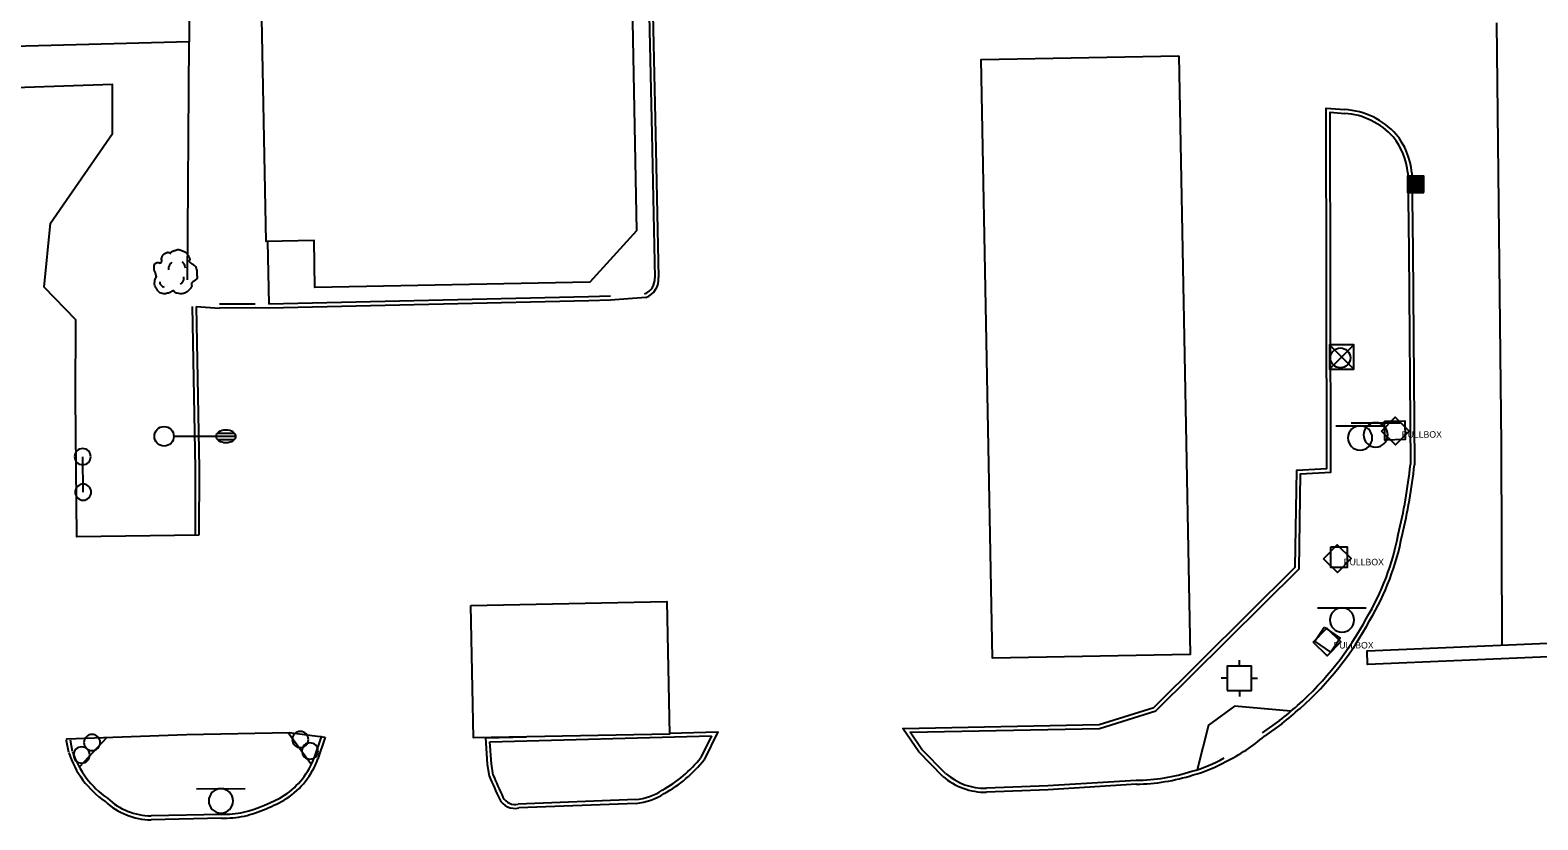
# Model space of a CAD drawing. Extents: x 2145380 to 2157287, y 139568 to 149130.
# Drawn here: x 2150453.6 to 2150685.4, y 145669.1 to 145790.5 of the extents above; entities that cross this region are included whole.
import ezdxf

# ---------------------------------------------------------------- set-up
doc = ezdxf.new("R2010")
doc.units = 0
for name, color, linetype in [('Default', 7, 'Continuous'), ('TOPO_Asphalt', 7, 'Continuous'), ('TOPO_Building', 7, 'Continuous'), ('TOPO_Concrete', 7, 'Continuous'), ('TOPO_Curb Back', 7, 'Continuous'), ('TOPO_Fence', 7, 'Continuous'), ('TOPO_Light Pole', 7, 'Continuous'), ('TOPO_Misc', 7, 'Continuous'), ('TOPO_Misc Line', 7, 'Continuous'), ('TOPO_Power Pullbox', 7, 'Continuous'), ('TOPO_Sidewalk', 7, 'Continuous'), ('TOPO_Sign', 7, 'Continuous'), ('TOPO_Traffic Signal', 7, 'Continuous'), ('TOPO_Tree', 7, 'Continuous'), ('TOPO_Wall Freestanding', 7, 'Continuous'), ('TOPO_Water Meter', 7, 'Continuous')]:
    doc.layers.add(name, color=color, linetype=linetype)

# ---------------------------------------------------------------- blocks, each defined once
blk = doc.blocks.new('TRFSIG')
at = {"layer": 'TOPO_Traffic Signal'}
for p, q in [((0.04, 4.66), (0.04, 7.04)), ((-4.7, -0.09), (-7.08, -0.09)), ((0.04, -4.83), (0.04, -7.22)), ((4.79, -0.09), (7.17, -0.09))]:
    blk.add_line(p, q, dxfattribs=at)
blk.add_lwpolyline([(-4.7, -4.85), (4.81, -4.83), (4.79, 4.67), (-4.72, 4.66), (-4.7, -4.85)], dxfattribs=at)
blk = doc.blocks.new('LP')
at = {"layer": 'TOPO_Light Pole'}
blk.add_line((3.81, 0), (20.32, 0), dxfattribs=at)
for points in [[(20.32, 0), (27.94, 0)], [(20.32, 0), (23.5, 0)], [(20.83, 1.27), (27.43, 1.27)], [(20.83, 1.27), (23.5, 1.27)], [(23.71, 1.27), (27.43, 1.27)], [(23.71, 0), (27.94, 0)], [(20.83, -1.27), (27.43, -1.27)], [(20.83, -1.27), (23.5, -1.27)], [(23.71, -1.27), (27.43, -1.27)]]:
    blk.add_lwpolyline(points, dxfattribs=at)
blk.add_circle((0, 0), 3.81, dxfattribs=at)
blk.add_ellipse((24.13, 0), major_axis=(3.81, 0), ratio=0.666667, dxfattribs=at)
blk = doc.blocks.new('POST')
at = {"layer": 'TOPO_Misc'}
for start, end in [(89.99996, 180.00004), (179.99996, 270.00004), (359.99996, 90.00004), (269.99996, 0.00004)]:
    blk.add_arc((-0.01, 0.03), 3.16, start, end, dxfattribs=at)
blk = doc.blocks.new('CB')
at = {"layer": 'TOPO_Misc'}
for p, q in [((-3.08, 2.99), (3.24, 2.99)), ((-3.08, 2.68), (3.24, 2.68)), ((-3.08, 2.36), (3.24, 2.36)), ((-3.08, 2.05), (3.24, 2.05)), ((-3.08, 1.73), (3.24, 1.73)), ((-3.08, 1.4), (3.24, 1.4)), ((-3.08, 1.1), (3.24, 1.1)), ((-3.08, 0.77), (3.24, 0.77)), ((-3.08, 0.46), (3.24, 0.46)), ((-3.08, 0.14), (3.24, 0.14)), ((-3.08, -0.17), (3.24, -0.17)), ((-3.08, -0.48), (3.24, -0.48)), ((-3.08, -0.8), (3.24, -0.8)), ((-3.08, -1.11), (3.26, -1.11)), ((-3.08, -1.43), (3.26, -1.43)), ((-3.08, -1.75), (3.26, -1.75)), ((-3.08, -2.07), (3.26, -2.07)), ((-3.08, -2.39), (3.26, -2.39)), ((-3.08, -2.7), (3.26, -2.7)), ((-3.08, -3.02), (3.26, -3.02))]:
    blk.add_line(p, q, dxfattribs=at)
blk.add_lwpolyline([(3.26, -3.29), (3.24, 3.05), (-3.09, 3.04), (-3.08, -3.3), (3.26, -3.29)], dxfattribs=at)
blk = doc.blocks.new('TREE')
at = {"layer": 'TOPO_Tree'}
for points in [[(-14.1, -0.4), (-14.2, 0.5), (-14.4, 1.4), (-14.6, 2.3), (-14.8, 3.2), (-15.5, 4), (-15.7, 4.9), (-15.8, 5.6), (-15.7, 6.3), (-15.7, 7), (-15.6, 7.9), (-15.7, 8.8), (-15.1, 9.7), (-14.6, 10.4), (-13.8, 10.5), (-13, 10.7), (-12.2, 11), (-11.1, 10), (-10.4, 10.7), (-9.4, 11.7), (-10.3, 13.3), (-9.8, 14.4), (-9.6, 15.1), (-9.3, 15.9), (-8.8, 16.5), (-8.2, 17.3), (-7.5, 17.7), (-6.7, 18.1), (-6.1, 18.4), (-5.6, 18.6), (-5.1, 18.7), (-4.5, 18.7), (-4, 18.5), (-3.5, 18.1)], [(-3.5, 17.6), (-3.1, 18.3), (-2.6, 18.8), (-1.9, 19.2), (-1, 19.7), (-0.2, 20), (0.7, 20.2), (1.6, 20.5), (2.5, 20.8), (3.4, 20.8), (4.1, 20.7), (4.8, 20.5), (5.5, 20.2), (6.4, 19.9), (7.3, 19.7), (8.2, 19.2), (9.4, 18.4), (10, 17.2), (10.8, 16), (11.2, 15.3), (11.6, 14.6), (11.9, 13.9), (12.2, 13.1), (11.4, 12), (11.9, 11.2), (12, 11), (12.2, 10.9), (12.4, 10.7), (12.9, 10.4), (13.5, 10), (14, 9.7), (14.7, 9.2), (15.4, 8.7), (16.1, 8.1), (16.7, 7.5), (16.9, 6.7), (17.1, 6), (17.6, 4.4), (17.7, 2.8), (17.7, 1.2), (17.7, -0.2), (17.8, -2.2), (16.6, -3), (15.5, -3.8), (14.3, -4.6), (13.2, -5.3)], [(13.2, -5.3), (13.3, -5.8), (13.4, -6.3), (13.4, -6.7), (13.8, -8.5), (12.2, -10), (10.8, -11.5), (10, -12.3), (9.1, -12.8), (8.2, -13.1), (6, -13.8), (3.3, -13.6), (1.3, -13.1), (0.5, -12.9), (-0.1, -11.4), (-0.8, -11.5), (-2, -11.6), (-3.3, -12.8), (-4.5, -13.1), (-6.1, -13.5), (-7.8, -14), (-9.3, -13.6), (-11.4, -13.1), (-12.8, -11.4), (-14.1, -9.4), (-15.3, -7.3), (-15.6, -5.1), (-15.1, -3), (-14.9, -1.9), (-13.9, -0.8), (-13.5, 0.1)], [(-4.2, 5.1), (-4.5, 6.1), (-4.3, 7.2), (-3.8, 8.2), (-3.3, 9.3), (-2.7, 10.3), (-1.6, 11)], [(5.9, 11.2), (6.5, 10.7), (7, 10.2), (7.4, 9.5), (7.9, 8.6), (8.3, 7.6), (8.5, 6.6)], [(-11.4, -4.5), (-11.5, -5.4), (-11, -6.3), (-10.1, -7.2), (-9.3, -8), (-8.5, -8.3), (-7.7, -8.1)], [(4.8, -6.3), (5.7, -5.7), (6.3, -4.9), (6.8, -3.9), (7.4, -2.8), (7.6, -1.7), (7.5, -0.6)]]:
    blk.add_open_spline(points, degree=3, dxfattribs=at)
blk = doc.blocks.new('pulbox')
at = {"layer": 'Default'}
blk.add_lwpolyline([(-5.38, -0.01), (-0.02, 5.42), (5.4, 0.06), (0.05, -5.36), (-5.38, -0.01)], dxfattribs=at)
blk.add_text('PULLBOX', height=2.54, dxfattribs=at).set_placement((2.54, -2.54))
blk = doc.blocks.new('WTRMTR')
at = {"layer": 'Default'}
blk.add_circle((0, 0), 3.89, dxfattribs=at)

msp = doc.modelspace()

# ---------------------------------------------------------------- linework, layer by layer
at = {"layer": 'TOPO_Asphalt'}
for p, q in [((2150479.12, 145747.97), (2150482.74, 145747.74)), ((2150490.31, 145747.73), (2150488.21, 145747.76)), ((2150548.29, 145749.38), (2150542.86, 145748.97))]:
    msp.add_line(p, q, dxfattribs=at)
for points in [[(2150479.57, 145712.84), (2150460.77, 145712.55), (2150460.61, 145734), (2150460.65, 145745.93), (2150455.78, 145750.97), (2150456.76, 145760.81), (2150466.27, 145774.6), (2150466.27, 145782.09), (2150445.27, 145781.39)], [(2150459.22, 145681.2), (2150459.23, 145681.51), (2150477.67, 145682.19), (2150493.45, 145682.52), (2150498.99, 145681.78)]]:
    msp.add_lwpolyline(points, dxfattribs=at)
msp.add_arc((2150626.83, 145700.66), 24.98, 295.202, 311.4607, dxfattribs=at)
at = {"layer": 'TOPO_Building'}
msp.add_lwpolyline([(2150545.73, 145818.58), (2150546.85, 145759.6), (2150539.66, 145751.71), (2150497.4, 145750.91), (2150497.26, 145758.14), (2150489.89, 145758), (2150488.64, 145824), (2150538.35, 145824.95), (2150538.47, 145818.44)], close=True, dxfattribs=at)
at = {"layer": 'TOPO_Concrete'}
for p, q in [((2150465.41, 145681.74), (2150461.17, 145677.17)), ((2150493.26, 145682.52), (2150496.85, 145677.59))]:
    msp.add_line(p, q, dxfattribs=at)
for points in [[(2150661.83, 145730.35), (2150664.95, 145730.43), (2150665.03, 145727.53), (2150661.91, 145727.44), (2150661.83, 145730.35)], [(2150653.57, 145711.03), (2150656.09, 145711.03), (2150656.1, 145707.88), (2150653.58, 145707.87), (2150653.57, 145711.03)], [(2150652.59, 145698.68), (2150655.04, 145697.01), (2150653.58, 145694.86), (2150651.13, 145696.52), (2150652.59, 145698.68)]]:
    msp.add_lwpolyline(points, dxfattribs=at)
at = {"layer": 'TOPO_Curb Back'}
for p, q in [((2150488.2, 145748.36), (2150482.74, 145748.34)), ((2150488.21, 145747.76), (2150482.74, 145747.74)), ((2150524.31, 145681.07), (2150558.35, 145681.99)), ((2150524.53, 145677.69), (2150524.31, 145681.07)), ((2150558.35, 145681.99), (2150556.73, 145678.63)), ((2150524.81, 145675.91), (2150524.53, 145677.69)), ((2150546.73, 145672.19), (2150528.67, 145671.49))]:
    msp.add_line(p, q, dxfattribs=at)
for points in [[(2150538.35, 145824.79), (2150548.63, 145825.11), (2150549.78, 145774.55), (2150550.24, 145752.43)], [(2150538.37, 145824.19), (2150548.05, 145824.49), (2150549.18, 145774.54), (2150549.64, 145752.4)], [(2150593.96, 145675.75), (2150590.24, 145679.51), (2150587.77, 145683.13), (2150617.99, 145683.73), (2150626.37, 145686.33), (2150648.12, 145707.9), (2150648.34, 145722.81), (2150653, 145723.08), (2150652.87, 145778.49), (2150655.76, 145778.27)], [(2150594.37, 145676.19), (2150590.7, 145679.9), (2150588.89, 145682.55), (2150618.05, 145683.13), (2150626.69, 145685.8), (2150648.71, 145707.65), (2150648.93, 145722.24), (2150653.6, 145722.52), (2150653.47, 145777.84), (2150655.72, 145777.68)], [(2150665.43, 145768.52), (2150665.59, 145756.62), (2150665.84, 145723.68)], [(2150666.03, 145768.55), (2150666.19, 145756.62), (2150666.44, 145723.65)], [(2150478.52, 145747.96), (2150478.98, 145723.11), (2150478.97, 145712.84)], [(2150479.12, 145747.97), (2150479.58, 145723.11), (2150479.57, 145712.84)], [(2150542.84, 145749.57), (2150539.48, 145749.47), (2150490.29, 145748.33)], [(2150542.86, 145748.97), (2150539.5, 145748.87), (2150490.31, 145747.73)], [(2150645.71, 145684.32), (2150643.02, 145682.43)], [(2150646.07, 145683.85), (2150643.37, 145681.94)], [(2150459.57, 145679.4), (2150459.22, 145681.2)], [(2150460.15, 145679.55), (2150459.81, 145681.31)], [(2150498.42, 145681.97), (2150497.29, 145678.63)], [(2150498.99, 145681.78), (2150497.86, 145678.43)], [(2150524.22, 145675.75), (2150523.93, 145677.63), (2150523.67, 145681.65), (2150529.87, 145681.82)], [(2150551.92, 145682.41), (2150559.32, 145682.61), (2150557.24, 145678.31)], [(2150623.67, 145675.14), (2150610.1, 145674.29), (2150600.64, 145673.92)], [(2150623.69, 145674.54), (2150610.13, 145673.69), (2150600.65, 145673.32)], [(2150546.77, 145671.59), (2150528.75, 145670.89)], [(2150483.02, 145669.91), (2150472.2, 145669.67)], [(2150483.02, 145669.31), (2150472.2, 145669.07)]]:
    msp.add_lwpolyline(points, dxfattribs=at)
for centre, radius, start, end in [((2150654.97, 145766.61), 11.69, 42.0292, 86.1316), ((2150654.97, 145766.61), 11.09, 42.1121, 86.144), ((2150655.21, 145767.61), 10.26, 5.1053, 38.8711), ((2150655.21, 145767.61), 10.86, 4.9837, 38.9595), ((2150547.24, 145752.2), 2.41, 290.4691, 4.7141), ((2150547.24, 145752.2), 3.01, 290.4666, 4.3443), ((2150580.46, 145733.03), 85.89, 346.4643, 353.7487), ((2150580.43, 145733.04), 86.52, 346.4744, 353.7701), ((2150624.9, 145720.4), 39.77, 329.2276, 349.1806), ((2150624.9, 145720.4), 40.37, 329.2458, 349.1614), ((2150615.97, 145723.23), 48.94, 311.6351, 331.7301), ((2150615.97, 145723.23), 49.54, 311.632, 331.7151), ((2150590.04, 145753.56), 88.84, 308.8016, 311.1385), ((2150589.97, 145753.64), 89.54, 308.7903, 311.1382), ((2150473.29, 145683.79), 14.41, 197.765, 235.5157), ((2150473.29, 145683.79), 13.81, 197.9153, 235.7052), ((2150486.04, 145682.8), 12, 303.8778, 339.6246), ((2150486.04, 145682.8), 12.6, 303.7838, 339.6693), ((2150540.92, 145691.32), 20.27, 299.1869, 321.2748), ((2150540.92, 145691.31), 20.87, 299.2381, 321.4639), ((2150626.64, 145697.07), 21.28, 285.2424, 299.6587), ((2150624.84, 145718.36), 108.66, 202.991, 204.9337), ((2150600.45, 145683.2), 9.28, 229.0681, 271.1304), ((2150623.21, 145704.89), 29.75, 270.8775, 287.6551), ((2150623.21, 145704.89), 30.35, 270.9041, 287.6326), ((2150626.64, 145697.07), 21.88, 285.276, 299.6576), ((2150625.16, 145718.49), 109.61, 202.9537, 204.9354), ((2150545.81, 145681.36), 9.21, 275.6866, 302.7947), ((2150600.45, 145683.2), 9.88, 228.934, 271.1653), ((2150472.33, 145679.58), 10.51, 226.8134, 269.3067), ((2150472.33, 145679.58), 9.91, 226.5506, 269.2478), ((2150479.67, 145695.48), 26.14, 284.9551, 299.9767), ((2150479.67, 145695.48), 26.74, 284.9086, 300.0201), ((2150528.15, 145673.51), 2.68, 207.1302, 282.8661), ((2150528.15, 145673.51), 2.08, 207.4289, 284.3), ((2150545.81, 145681.36), 9.81, 275.5792, 302.6836), ((2150483.06, 145687.81), 17.9, 269.8599, 280.8026), ((2150483.06, 145687.8), 18.49, 269.8824, 280.8733)]:
    msp.add_arc(centre, radius, start, end, dxfattribs=at)
at = {"layer": 'TOPO_Fence'}
msp.add_lwpolyline([(2150553.45, 145951.86), (2150555.13, 145907.81), (2150628.34, 145899.05), (2150631.29, 145841.97), (2150539.13, 145839.51), (2150509.05, 145838.3), (2150507.95, 145837.12), (2150477.94, 145837.44), (2150478.08, 145788.67)], dxfattribs=at)
at = {"layer": 'TOPO_Misc'}
msp.add_line((2150653.39, 145742.1), (2150657.14, 145738.37), dxfattribs=at)
msp.add_lwpolyline([(2150653.4, 145738.36), (2150657.14, 145738.37), (2150657.13, 145742.11), (2150653.39, 145742.1), (2150653.4, 145738.36), (2150657.13, 145742.11)], dxfattribs=at)
at = {"layer": 'TOPO_Misc Line'}
msp.add_lwpolyline([(2150679.08, 145791.61), (2150679.8, 145726.79), (2150679.88, 145695.93)], dxfattribs=at)
for points in [[(2150630.24, 145786.51), (2150631.97, 145694.47), (2150601.58, 145693.9), (2150599.85, 145785.94)], [(2150521.37, 145702.04), (2150551.51, 145702.64), (2150551.92, 145682.26), (2150521.78, 145681.65)], [(2150702.72, 145694.79), (2150659.25, 145692.95), (2150659.16, 145695.05), (2150702.63, 145696.89)]]:
    msp.add_lwpolyline(points, close=True, dxfattribs=at)
at = {"layer": 'TOPO_Sidewalk'}
msp.add_line((2150490.11, 145758), (2150490.29, 145748.33), dxfattribs=at)
msp.add_lwpolyline([(2150647.43, 145685.75), (2150638.78, 145686.52), (2150634.77, 145683.6), (2150633.06, 145676.78)], dxfattribs=at)
at = {"layer": 'TOPO_Sign'}
for points in [[(2150654.34, 145729.64), (2150661.84, 145729.65)], [(2150656.74, 145730.12), (2150664.23, 145730.12)], [(2150658.09, 145729.64), (2150658.09, 145729.64)], [(2150660.49, 145730.11), (2150660.49, 145730.11)], [(2150656.23, 145727.78), (2150656.23, 145727.78)], [(2150658.62, 145728.25), (2150658.62, 145728.25)], [(2150659.96, 145727.78), (2150659.96, 145727.78)], [(2150662.36, 145728.25), (2150662.36, 145728.25)], [(2150461.77, 145719.44), (2150461.7, 145724.88)], [(2150658.09, 145725.91), (2150658.09, 145725.91)], [(2150660.49, 145726.38), (2150660.49, 145726.38)], [(2150651.55, 145701.66), (2150659.04, 145701.67)], [(2150655.3, 145701.66), (2150655.3, 145701.66)], [(2150653.43, 145699.79), (2150653.43, 145699.79)], [(2150657.17, 145699.79), (2150657.17, 145699.79)], [(2150655.3, 145697.92), (2150655.3, 145697.92)], [(2150479.19, 145673.85), (2150486.69, 145673.86)], [(2150482.94, 145673.85), (2150482.94, 145673.85)], [(2150481.08, 145671.98), (2150481.08, 145671.98)], [(2150484.81, 145671.98), (2150484.81, 145671.98)], [(2150482.94, 145670.11), (2150482.94, 145670.11)]]:
    msp.add_lwpolyline(points, dxfattribs=at)
for centre, start, end in [((2150658.09, 145727.78), 90, 180), ((2150658.09, 145727.78), 360, 90), ((2150660.49, 145728.25), 90, 180), ((2150660.49, 145728.25), 360, 90), ((2150658.09, 145727.78), 180, 270), ((2150658.09, 145727.78), 270, 0), ((2150660.49, 145728.25), 180, 270), ((2150660.49, 145728.25), 270, 0), ((2150655.3, 145699.79), 90, 180), ((2150655.3, 145699.79), 360, 90), ((2150655.3, 145699.79), 180, 270), ((2150655.3, 145699.79), 270, 0), ((2150482.94, 145671.98), 90, 180), ((2150482.94, 145671.98), 360, 90), ((2150482.94, 145671.98), 180, 270), ((2150482.94, 145671.98), 270, 0)]:
    msp.add_arc(centre, 1.87, start, end, dxfattribs=at)
at = {"layer": 'TOPO_Wall Freestanding'}
msp.add_lwpolyline([(2150477.8, 145752.07), (2150478.08, 145788.67), (2150449.11, 145787.89), (2150414.36, 145787.3), (2150414.4, 145789.73)], dxfattribs=at)

# ---------------------------------------------------------------- block references
at = {"layer": 'TOPO_Light Pole', "xscale": 0.39370000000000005, "yscale": 0.3937000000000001}
msp.add_blockref('LP', (2150474.21, 145728.03), dxfattribs=at)
at = {"layer": 'TOPO_Misc', "xscale": 0.39370000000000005, "yscale": 0.3937000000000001}
for name, p in [('CB', (2150666.61, 145766.81)), ('POST', (2150461.7, 145724.88)), ('POST', (2150461.77, 145719.44)), ('POST', (2150463.14, 145680.95)), ('POST', (2150495.15, 145681.4)), ('POST', (2150496.64, 145679.64)), ('POST', (2150461.53, 145679.03))]:
    msp.add_blockref(name, p, dxfattribs=at)
at = {"layer": 'TOPO_Power Pullbox', "xscale": 0.39370000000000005, "yscale": 0.3937000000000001}
for p in [(2150663.5, 145728.82), (2150654.58, 145709.2), (2150653, 145696.41)]:
    msp.add_blockref('pulbox', p, dxfattribs=at)
at = {"layer": 'TOPO_Traffic Signal', "xscale": 0.39370000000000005, "yscale": 0.3937000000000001}
msp.add_blockref('TRFSIG', (2150639.52, 145690.86), dxfattribs=at)
at = {"layer": 'TOPO_Tree', "xscale": 0.19685000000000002, "yscale": 0.19685000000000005}
msp.add_blockref('TREE', (2150475.78, 145752.64), dxfattribs=at)
at = {"layer": 'TOPO_Water Meter', "xscale": 0.39370000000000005, "yscale": 0.3937000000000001}
msp.add_blockref('WTRMTR', (2150655.06, 145740.09), dxfattribs=at)

doc.saveas('drawing.dxf')
